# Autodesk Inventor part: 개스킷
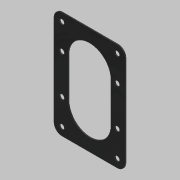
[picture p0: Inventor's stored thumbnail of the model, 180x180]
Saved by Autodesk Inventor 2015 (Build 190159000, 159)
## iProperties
Created: 2019-03
Part Number: 개스킷
Material: 고무
Document SubType Name: Modeling
Designer: mduedu
Density: 1 g/cm^3
Appearance: 고무 - 검은색 - 버전 1.1
Author: mduedu
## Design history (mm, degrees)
sketch "스케치1"
  geometry: L1 (-60, 40)-(60, 40); L2 (60, 40)-(60, -40); L3 (60, -40)-(-60, -40); L4 (-60, -40)-(-60, 40); L5 (-60, 40)-(60, -40); L6 (60, 40)-(-60, -40); 1 further point
  constraints: 12 end point, 2 midpoint, 2 parallel, 1 horizontal, 1 perpendicular
  dimensions: "d21" = 120 distance of L2.end L3.end; "d22" = 80 distance of L1.end L2.end
extrude "돌출1" new body sketch "스케치1" distance "d3" = 1; taper "d4" = 0 deg
fillet "모깎기1" dims "d5" = 9
sketch "스케치2" dims "d6" = 48
  geometry: L1 (-24, -22)-(24, -22); L2 (24, -22)-(24, 22); L3 (24, 22)-(-24, 22); L4 (-24, 22)-(-24, -22); L5 (-24, -22)-(24, 22); L6 (24, -22)-(-24, 22); 3 further points
  constraints: 12 end point, 4 midpoint, 2 horizontal alignment, 2 parallel, 1 horizontal, 1 perpendicular, 4 other
  dimensions: "d8" = 22 distance from line of L3 point (0, 0)
extrude "돌출2" cut sketch "스케치2" stored distance "d9" = 1; taper "d10" = 0 deg
sketch "스케치3"
  geometry: L1 (-24, -22)-(-24, 22) reference; L2 (24, 22)-(24, -22) reference; L3 (40, -51)-(40, 51) reference; L4 (31, 60)-(-31, 60) reference; L5 (-40, 51)-(-40, -51) reference; L6 (-31, -60)-(31, -60) reference; L7 (-31, 51)-(31, 51); L8 (31, 51)-(31, -51); L9 (31, -51)-(-31, -51); L10 (-31, -51)-(-31, 51); A1 r 24 centre (0, 22) between (24, 22) and (-24, 22) reference; A2 r 24 centre (0, -22) between (-24, -22) and (24, -22) reference; A3 r 9 centre (31, -51) between (31, -60) and (40, -51) reference; A4 r 9 centre (31, 51) between (40, 51) and (31, 60) reference; A5 r 9 centre (-31, 51) between (-31, 60) and (-40, 51) reference; A6 r 9 centre (-31, -51) between (-40, -51) and (-31, -60) reference; 9 further points
  constraints: 8 end point, 4 coincident, 4 horizontal alignment, 4 point on line, 2 parallel, 1 horizontal, 1 perpendicular
  dimensions: "d23" = 102 distance between parallel lines of L9 L7 (derived); "d24" = 29 distance from line of point (-31, 22) L7 (derived); "d25" = 29 distance from line of point (-31, -22) L9 (derived)
hole "구멍1" sketch "스케치3" at (-31, 51), (31, 51), (31, -51), (-31, -51), (-31, -22), (-31, 22), (31, 22), (31, -22) diameter "d14" = 5.5; stored, may be unused: countersink angle "d18" = 90 deg, drill point angle "d20" = 118 deg; dims "d15" = 6, "d16" = 4, "d17" = 2, "d19" = 8
node "솔리드1"
node "투영된 루프1"
